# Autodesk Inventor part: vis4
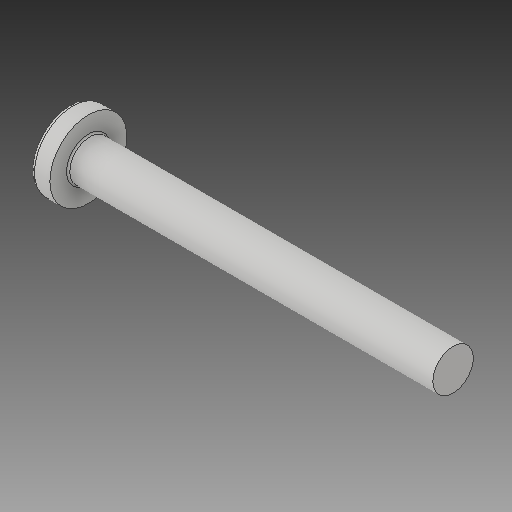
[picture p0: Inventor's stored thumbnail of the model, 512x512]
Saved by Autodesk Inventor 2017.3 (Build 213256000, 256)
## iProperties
Created: 1999-08
Part Number: vis4
Material: Générique
Document SubType Name: Modeling
Designer: ficho
Density: 1 g/cm^3
Appearance: Par défaut
Author: ficho
Sending System: SolidWorks 2009
Last Author: christophe
Last Saved: 2011-01-17
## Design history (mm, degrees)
feature "RecessCore"
node "Solide1"
